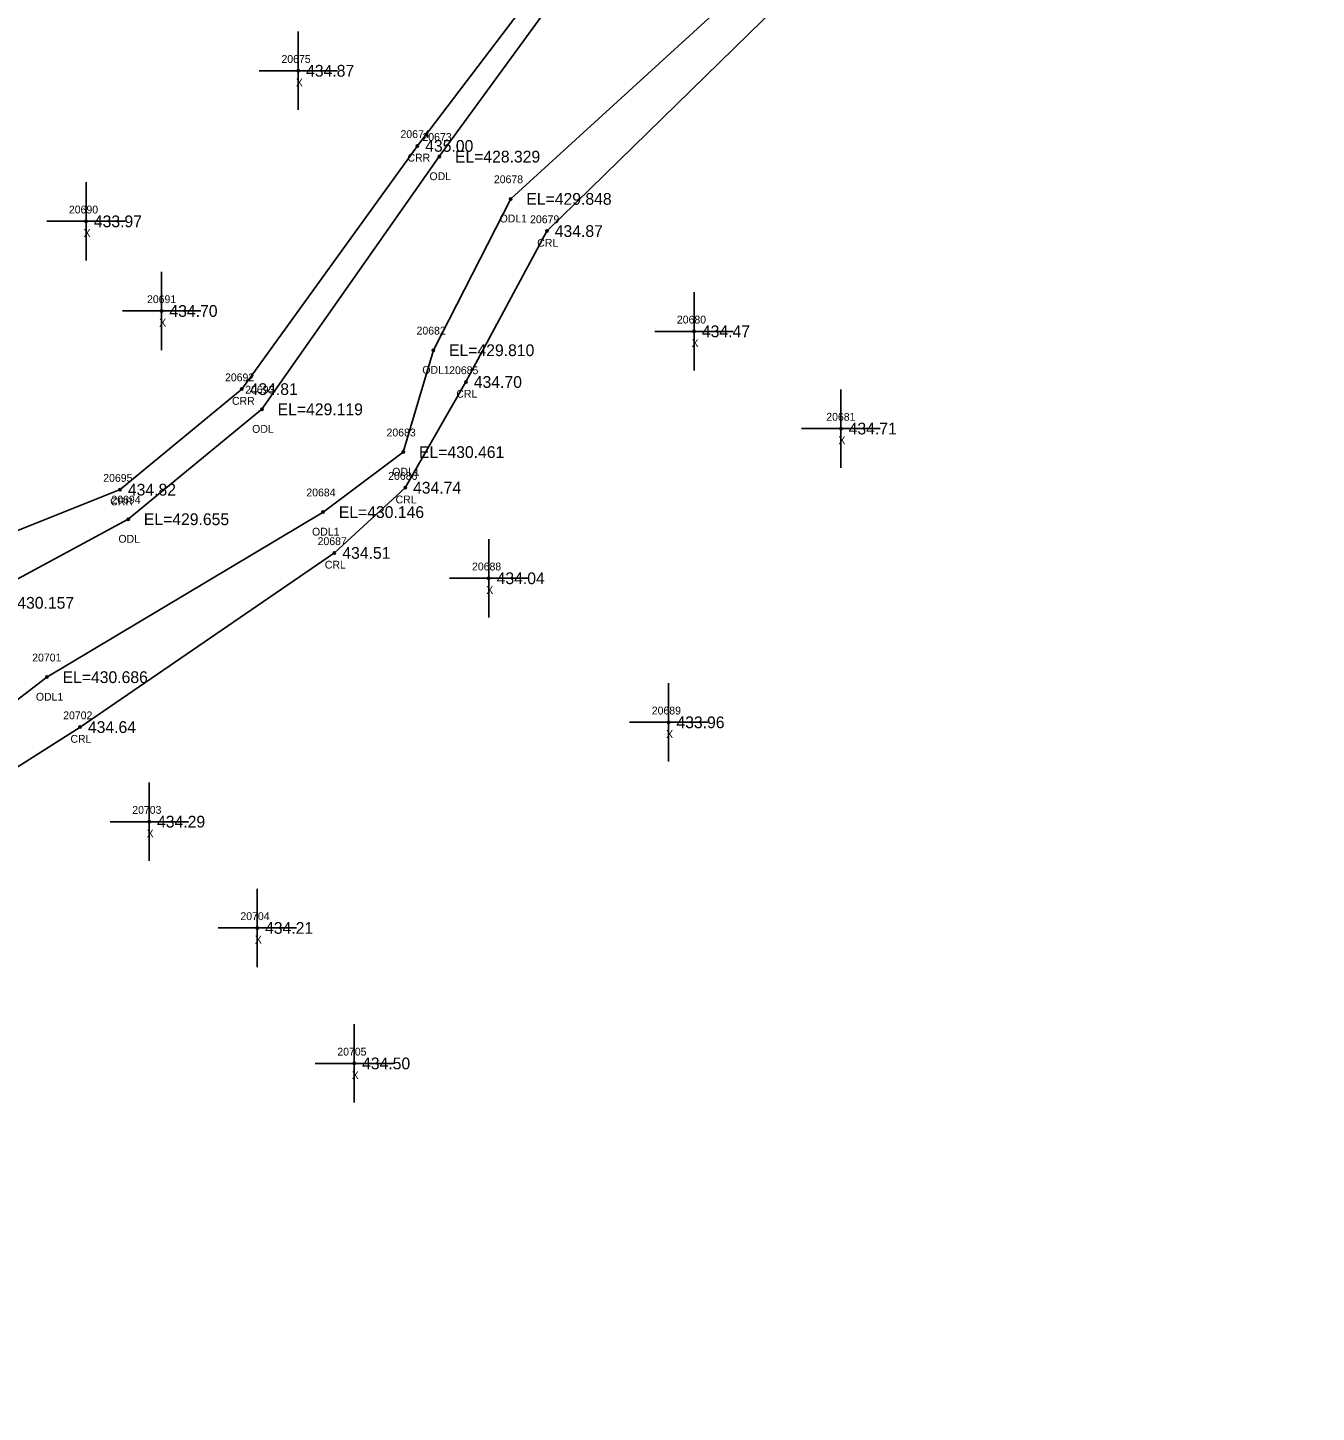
# Model space of a CAD drawing. Extents: x 1613836 to 1615109, y 777151 to 778248.
# Drawn here: x 1614288 to 1614452.4, y 777274.4 to 777451 of the extents above; entities that cross this region are included whole.
import ezdxf

# ---------------------------------------------------------------- set-up
doc = ezdxf.new("R2010")
doc.units = 0
for name, color, linetype in [('RD_EX_H2O', 7, 'Continuous'), ('RD_EX_H2O_txCode', 7, 'Continuous'), ('RD_EX_Misc', 7, 'Continuous'), ('RD_EX_Misc_txCode', 7, 'Continuous'), ('RD_EX_TX_H2O_ELEV', 7, 'Continuous'), ('RD_EX_TX_Misc_ELEV', 7, 'Continuous'), ('RD_SMD_Locator', 7, 'Continuous')]:
    doc.layers.add(name, color=color, linetype=linetype)

msp = doc.modelspace()

# ---------------------------------------------------------------- linework, layer by layer
at = {"layer": 'RD_EX_H2O'}
for points in [[(1614454.05, 777670.72), (1614436.75, 777625.46), (1614428.25, 777606.48), (1614422.27, 777582.64), (1614421.12, 777572.72), (1614422.32, 777559.44), (1614418.89, 777533.48), (1614401.74, 777483.1), (1614391.89, 777467.73), (1614349.64, 777429.15), (1614339.78, 777409.85), (1614335.95, 777396.86), (1614325.72, 777389.21), (1614290.49, 777368.16), (1614258.86, 777343.9), (1614240.94, 777335.51), (1614216.63, 777330.83), (1614183.69, 777312.56), (1614168.44, 777300.41), (1614159.13, 777291.4), (1614144.06, 777280.87), (1614131.88, 777280.26), (1614120.23, 777291.04), (1614099.45, 777295.34)], [(1614459.87, 777668.19), (1614440.89, 777623.61), (1614431.44, 777603.44), (1614426.49, 777580.47), (1614427.73, 777573.1), (1614426.99, 777558.49), (1614422.1, 777533.28), (1614405.02, 777481.5), (1614394.67, 777464.56), (1614354.26, 777425.05), (1614343.94, 777405.8), (1614336.19, 777392.32), (1614327.17, 777384), (1614294.72, 777361.79), (1614260.51, 777340.05), (1614241.21, 777332.56), (1614218.51, 777327.29), (1614184.87, 777310.82), (1614170.3, 777296.09), (1614164.11, 777287.12), (1614144.8, 777274.41), (1614131.24, 777274.67), (1614118.95, 777276.86), (1614096.34, 777283.46)], [(1614355.46, 777459.21), (1614337.74, 777435.91), (1614315.35, 777404.89), (1614299.82, 777392.07), (1614278.11, 777383.41), (1614250.11, 777357.81), (1614234.72, 777351.23), (1614210.69, 777344.44), (1614182.75, 777330.65), (1614173.16, 777323.23), (1614157.31, 777313.16), (1614145.24, 777309.88), (1614127.38, 777304.3), (1614101.74, 777312.03)], [(1614356.26, 777456.14), (1614340.53, 777434.54), (1614317.92, 777402.32), (1614300.86, 777388.3), (1614281.09, 777377.64), (1614252, 777356.09), (1614236.11, 777347.19), (1614212.88, 777342.6), (1614184.13, 777328.73), (1614174.35, 777321.16), (1614160.03, 777309.56), (1614147.17, 777307.71), (1614127.22, 777301.43), (1614100.44, 777304.89)]]:
    msp.add_lwpolyline(points, dxfattribs=at)
at = {"layer": 'RD_EX_Misc'}
for p, q in [((1614322.55, 777440.49), (1614322.55, 777450.49)), ((1614317.55, 777445.49), (1614327.55, 777445.49)), ((1614295.48, 777421.29), (1614295.48, 777431.29)), ((1614290.48, 777426.29), (1614300.48, 777426.29)), ((1614305.12, 777409.86), (1614305.12, 777419.86)), ((1614373.03, 777407.26), (1614373.03, 777417.26)), ((1614300.12, 777414.86), (1614310.12, 777414.86)), ((1614368.03, 777412.26), (1614378.03, 777412.26)), ((1614391.75, 777394.86), (1614391.75, 777404.86)), ((1614386.75, 777399.86), (1614396.75, 777399.86)), ((1614346.85, 777375.77), (1614346.85, 777385.77)), ((1614341.85, 777380.77), (1614351.85, 777380.77)), ((1614369.78, 777357.4), (1614369.78, 777367.4)), ((1614364.78, 777362.4), (1614374.78, 777362.4)), ((1614303.54, 777344.73), (1614303.54, 777354.73)), ((1614298.54, 777349.73), (1614308.54, 777349.73)), ((1614317.32, 777331.18), (1614317.32, 777341.18)), ((1614312.32, 777336.18), (1614322.32, 777336.18)), ((1614329.69, 777313.9), (1614329.69, 777323.9)), ((1614324.69, 777318.9), (1614334.69, 777318.9))]:
    msp.add_line(p, q, dxfattribs=at)
at = {"layer": 'RD_SMD_Locator'}
for centre in [(1614322.55, 777445.49), (1614337.74, 777435.91), (1614340.53, 777434.54), (1614349.64, 777429.15), (1614295.48, 777426.29), (1614354.26, 777425.05), (1614305.12, 777414.86), (1614373.03, 777412.26), (1614339.78, 777409.85), (1614343.94, 777405.8), (1614315.35, 777404.89), (1614317.92, 777402.32), (1614391.75, 777399.86), (1614335.95, 777396.86), (1614299.82, 777392.07), (1614336.19, 777392.32), (1614300.86, 777388.3), (1614325.72, 777389.21), (1614327.17, 777384), (1614346.85, 777380.77), (1614290.49, 777368.16), (1614294.72, 777361.79), (1614369.78, 777362.4), (1614303.54, 777349.73), (1614317.32, 777336.18), (1614329.69, 777318.9)]:
    msp.add_circle(centre, 0.15, dxfattribs=at)

# ---------------------------------------------------------------- texts
at = {"layer": 'RD_EX_H2O_txCode'}
for s, p in [('20674', (1614335.59, 777436.91)), ('20673', (1614338.39, 777436.54)), ('CRR', (1614336.48, 777433.91)), ('ODL', (1614339.29, 777431.54)), ('20678', (1614347.5, 777431.15)), ('ODL1', (1614348.23, 777426.15)), ('20679', (1614352.12, 777426.05)), ('CRL', (1614353.03, 777423.05)), ('20682', (1614337.64, 777411.85)), ('ODL1', (1614338.37, 777406.85)), ('20685', (1614341.8, 777406.8)), ('20692', (1614313.21, 777405.89)), ('CRR', (1614314.1, 777402.89)), ('20693', (1614315.78, 777404.32)), ('CRL', (1614342.71, 777403.8)), ('ODL', (1614316.67, 777399.32)), ('20683', (1614333.81, 777398.86)), ('ODL1', (1614334.54, 777393.86)), ('20695', (1614297.68, 777393.07)), ('20686', (1614334.02, 777393.32)), ('20684', (1614323.58, 777391.21)), ('CRL', (1614334.96, 777390.32)), ('CRR', (1614298.57, 777390.07)), ('20694', (1614298.72, 777390.3)), ('ODL', (1614299.62, 777385.3)), ('ODL1', (1614324.31, 777386.21)), ('20687', (1614325.02, 777385)), ('CRL', (1614325.94, 777382)), ('20701', (1614288.62, 777370.16)), ('ODL1', (1614289.09, 777365.16)), ('20702', (1614292.57, 777362.79)), ('CRL', (1614293.5, 777359.79))]:
    msp.add_text(s, height=1, dxfattribs=at).set_placement(p)
at = {"layer": 'RD_EX_Misc_txCode'}
for s, p in [('20675', (1614320.41, 777446.49)), ('X', (1614322.24, 777443.49)), ('20690', (1614293.3, 777427.29)), ('X', (1614295.17, 777424.29)), ('20691', (1614303.26, 777415.86)), ('X', (1614304.81, 777412.86)), ('20680', (1614370.84, 777413.26)), ('X', (1614372.71, 777410.26)), ('20681', (1614389.89, 777400.86)), ('X', (1614391.44, 777397.86)), ('20688', (1614344.71, 777381.77)), ('X', (1614346.53, 777378.77)), ('20689', (1614367.64, 777363.4)), ('X', (1614369.46, 777360.4)), ('20703', (1614301.38, 777350.73)), ('X', (1614303.22, 777347.73)), ('20704', (1614315.17, 777337.18)), ('X', (1614317.01, 777334.18)), ('20705', (1614327.53, 777319.9)), ('X', (1614329.37, 777316.9))]:
    msp.add_text(s, height=1, dxfattribs=at).set_placement(p)
at = {"layer": 'RD_EX_TX_H2O_ELEV'}
for s, p in [('435.00', (1614338.74, 777435.16)), ('EL=428.329', (1614342.53, 777433.79)), ('EL=429.848', (1614351.64, 777428.4)), ('434.87', (1614355.26, 777424.3)), ('EL=429.810', (1614341.78, 777409.1)), ('434.81', (1614316.35, 777404.14)), ('434.70', (1614344.94, 777405.05)), ('EL=429.119', (1614319.92, 777401.57)), ('EL=430.461', (1614337.95, 777396.11)), ('434.74', (1614337.19, 777391.57)), ('434.82', (1614300.82, 777391.32)), ('EL=430.146', (1614327.72, 777388.46)), ('EL=429.655', (1614302.86, 777387.55)), ('434.51', (1614328.17, 777383.25)), ('EL=430.157', (1614283.09, 777376.89)), ('EL=430.686', (1614292.49, 777367.41)), ('434.64', (1614295.72, 777361.04))]:
    msp.add_text(s, height=1.5, dxfattribs=at).set_placement(p)
at = {"layer": 'RD_EX_TX_Misc_ELEV'}
for s, p in [('434.87', (1614323.55, 777444.74)), ('433.97', (1614296.48, 777425.54)), ('434.70', (1614306.12, 777414.11)), ('434.47', (1614374.03, 777411.51)), ('434.71', (1614392.75, 777399.11)), ('434.04', (1614347.85, 777380.02)), ('433.96', (1614370.78, 777361.65)), ('434.29', (1614304.54, 777348.98)), ('434.21', (1614318.32, 777335.43)), ('434.50', (1614330.69, 777318.15))]:
    msp.add_text(s, height=1.5, dxfattribs=at).set_placement(p)

doc.saveas('drawing.dxf')
